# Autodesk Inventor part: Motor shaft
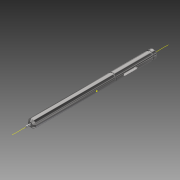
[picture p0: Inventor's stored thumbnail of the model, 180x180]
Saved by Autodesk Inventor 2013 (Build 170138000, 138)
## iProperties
Created: 2008-06
Part Number: Motor shaft
Document SubType Name: Modeling
Designer: tangg
Density: 7.84 g/cm^3
Mass: 17.005 g
Surface Area: 63.6795 cm^2
Volume: 17.005 cm^3
Material: Steel, High Strength Low Alloy
Author: tangg
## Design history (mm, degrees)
sketch "Sketch1"
  geometry: C1 r 5 at (0, 0); 1 further point
  constraints: 1 centre point, 1 coincident
  dimensions: "d0" = 10 diameter of C1
extrude "Extrusion1" new body sketch "Sketch1" stored distance "d1" = 152.4; taper "d2" = 0 deg
workplane "Work Plane4"
workplane "Work Plane5"
workplane "Work Plane6"
sketch "Sketch6"
  geometry: 1 further point
sketch "Sketch7"
  geometry: L1 (0, 106.68)-(0, -106.68) reference; L2 (-1.5, -49.215)-(-1.527, -34.925); L3 (1.473, -34.919)-(1.5, -49.21); L4 (-1.5, -49.215)-(1.5, -49.21); L5 (-1.527, -34.925)-(1.473, -34.919); A1 r 1.5 centre (0, -49.212) between (-1.5, -49.215) and (1.5, -49.21); A2 r 1.5 centre (-0.027, -34.922) between (1.473, -34.919) and (-1.527, -34.925); 2 further points
  constraints: 8 end point, 5 point on circle, 3 tangent, 2 centre point, 2 midpoint, 1 coincident, 1 point on line
  dimensions: "d28" = 3 distance between parallel lines of L2 L3
extrude "Extrusion2" cut sketch "Sketch7" distance "d29" = 3; taper "d30" = 0 deg
chamfer "Chamfer2" distance "d42" = 2; stored, may be unused: second distance "d43" = 2, angle "d44" = 45 deg
chamfer "Chamfer3" distance "d45" = 2; stored, may be unused: second distance "d46" = 2, angle "d47" = 45 deg
sketch "Sketch8"
  geometry: C1 r 1 at (0, 0); 1 further point
  constraints: 1 centre point, 1 coincident
  dimensions: "d48" = 2 diameter of C1
extrude "Extrusion3" join sketch "Sketch8" distance "d49" = 6; taper "d50" = 0 deg
fillet "Fillet1" dims "d51" = 0.2
sketch "Sketch9"
  geometry: L1 (-5, -74.2)-(5, -74.2) reference; L2 (-1.5, -49.215)-(-1.527, -34.925) reference; L3 (1.473, -34.919)-(1.5, -49.21) reference; L4 (5, 74.2)-(-5, 74.2) reference; L5 (-5, -74.2)-(-5, 74.2) reference; L6 (0, -103.88)-(0, 103.88) reference; C1 r 1 at (-5, -69.85); C2 r 0.75 at (-5, -23.812); 3 further points
  constraints: 2 centre point, 2 point on line, 4 other
  dimensions: "d53" = 2 diameter of C1; "d54" = 1.5 diameter of C2
revolve "Revolution4" sketch "Sketch9" stored, may be unused: angle "d52" = 90 deg
body "Solid1"
node "Projected Loop3"
other parameters: "d27" = -2
